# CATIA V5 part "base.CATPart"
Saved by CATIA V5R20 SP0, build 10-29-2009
Part number: base
Publications: "base_bati", "base_tige1", "base_tige2", "base_pivot1", "base_pivot2"
Bounding box of the stored display mesh (mm): x -10 to 110, y -150 to 150, z -250 to 0
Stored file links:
  C:\Users\Noëllie\Documents\IFMA\2A\S3\IAO\Projet Artobolevski\Catia\base.CATPart
  C:\Users\Noëllie\Documents\IFMA\2A\S3\IAO\Projet Artobolevski\Catia\Artobolevski 782.CATProduct
  C:\Users\Noëllie\Documents\IFMA\2A\S3\IAO\Projet Artobolevski\Catia\Squelette_general.CATPart
  C:\Users\Noëllie\Documents\IFMA\2A\S3\IAO\Projet Artobolevski\Catia\plateau_2.CATPart
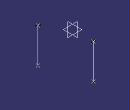
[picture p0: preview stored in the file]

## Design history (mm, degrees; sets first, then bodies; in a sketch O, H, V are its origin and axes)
Set1
  Point1 "b_1": linked copy from another document
  Point2 "b_2": linked copy from another document
  Point3 "A1": linked copy from another document
  Point4 "A2": linked copy from another document
Body1 (main body)
  Line1 "base_tige1": type PtPt, FirstPoint Point1, SecondPoint Point3
  Line2 "base_tige2": type PtPt, FirstPoint Point2, SecondPoint Point4
  Line3 "base_pivot1": type PtDir, RefPoint Point3, Direction yz-plane, Start 10, End -10
  Line4 "base_pivot2": type PtDir, RefPoint Point4, Direction yz-plane, Start 10, End -10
